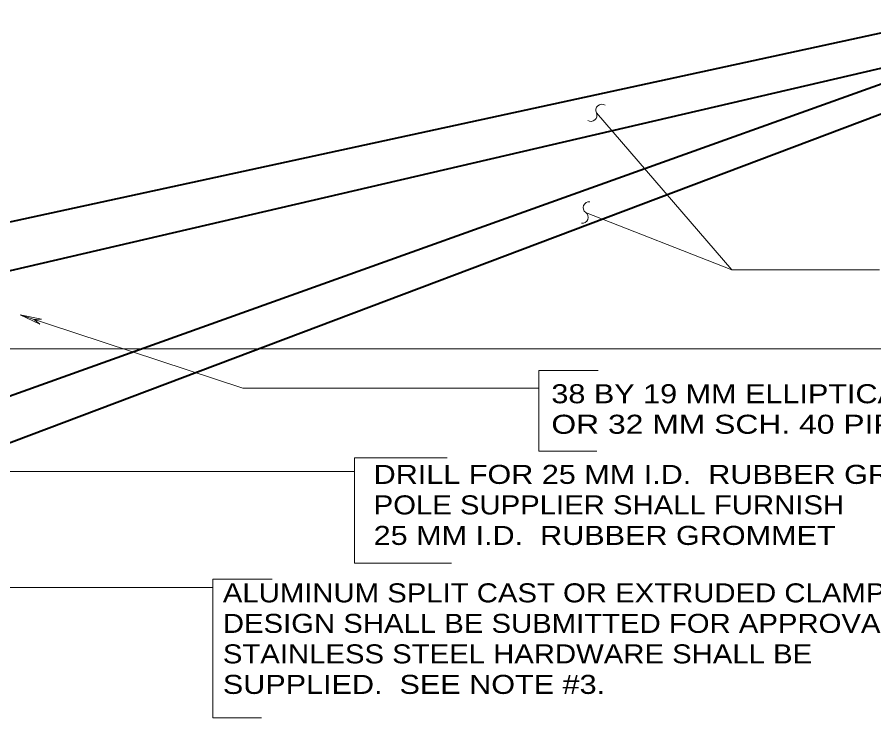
# Model space of a CAD drawing. Extents: x 312583 to 312854, y 144418 to 144597.
# Drawn here: x 312655.88 to 312690.06, y 144532.78 to 144560.74 of the extents above; entities that cross this region are included whole.
import ezdxf

# ---------------------------------------------------------------- set-up
doc = ezdxf.new("R2010")
doc.units = 0
doc.header["$LTSCALE"] = 0.3
doc.layers.add('1', color=7, linetype='Continuous', lineweight=35)

msp = doc.modelspace()

# ---------------------------------------------------------------- linework, layer by layer
at = {"layer": '1', "lineweight": 40}
for p, q in [((312642.9736, 144549.8358), (312705.979, 144563.4998)), ((312642.9736, 144547.6856), (312698.2854, 144560.5489)), ((312642.9736, 144541.1052), (312695.2125, 144559.8246)), ((312642.9736, 144539.0007), (312695.3421, 144558.7723))]:
    msp.add_line(p, q, dxfattribs=at)
at = {"layer": '1', "lineweight": 13}
for p, q in [((312684.3926, 144550.6593), (312678.5595, 144552.9468)), ((312664.8879, 144545.9318), (312656.0048, 144548.8598)), ((312656.0048, 144548.8598), (312656.7901, 144548.4938)), ((312656.0048, 144548.8598), (312656.8511, 144548.692)), ((312656.8511, 144548.692), (312656.5614, 144548.6768)), ((312656.7901, 144548.4938), (312656.5614, 144548.6768)), ((312740.9778, 144547.5102), (312630.9044, 144547.5102)), ((312676.6914, 144543.4156), (312676.6914, 144546.6409)), ((312676.6914, 144546.6409), (312679.0628, 144546.6409)), ((312676.6914, 144545.9318), (312664.8879, 144545.9318)), ((312676.6914, 144543.4156), (312679.0018, 144543.4156)), ((312669.3332, 144538.9549), (312669.3332, 144543.1487)), ((312669.3332, 144543.1487), (312673.039, 144543.1487)), ((312669.3332, 144542.6073), (312648.7229, 144542.6073)), ((312669.3332, 144538.9549), (312673.2068, 144538.9549)), ((312663.6908, 144532.7787), (312663.6908, 144538.3144)), ((312663.6908, 144538.3144), (312666.0545, 144538.3144)), ((312663.6908, 144537.9866), (312642.7068, 144537.9866)), ((312663.6908, 144532.7787), (312665.6275, 144532.7787))]:
    msp.add_line(p, q, dxfattribs=at)
msp.add_lwpolyline([(312690.2868, 144550.6593), (312684.3926, 144550.6593), (312678.9941, 144556.9194)], dxfattribs=at)
for centre, start, end in [((312679.2067, 144557.0236), 55.80156, 205.80156), ((312678.7778, 144556.8162), 235.80156, 25.80156), ((312678.7041, 144553.1367), 83.62126, 233.62126), ((312678.4216, 144552.7531), 263.62126, 53.62126)]:
    msp.add_arc(centre, 0.2382, start, end, dxfattribs=at)

# ---------------------------------------------------------------- texts
at = {"layer": '1'}
for s, width, p in [('38 BY 19 MM ELLIPTICAL EXTRUDED STRUT ALUM. ALLOY 6061-T6', 1.2, (312677.1946, 144545.3319)), ('OR 32 MM SCH. 40 PIPE ALUM.  ALLOY 6063-T6', 1.25, (312677.1946, 144544.1144)), ('DRILL FOR 25 MM I.D.  RUBBER GROMMET', 1.2, (312670.1034, 144542.1142)), ('POLE SUPPLIER SHALL FURNISH', 1.15, (312670.1034, 144540.8967)), ('25 MM I.D.  RUBBER GROMMET', 1.2, (312670.1034, 144539.6792)), ('ALUMINUM SPLIT CAST OR EXTRUDED CLAMPS.', 1.15, (312664.0872, 144537.3867)), ('DESIGN SHALL BE SUBMITTED FOR APPROVAL.', 1.15, (312664.0872, 144536.1692)), ('STAINLESS STEEL HARDWARE SHALL BE', 1.15, (312664.0872, 144534.9517)), ('SUPPLIED.  SEE NOTE #3.', 1.2, (312664.0872, 144533.7342))]:
    msp.add_text(s, height=0.76, dxfattribs=dict(at, width=width)).set_placement(p)

doc.saveas('drawing.dxf')
